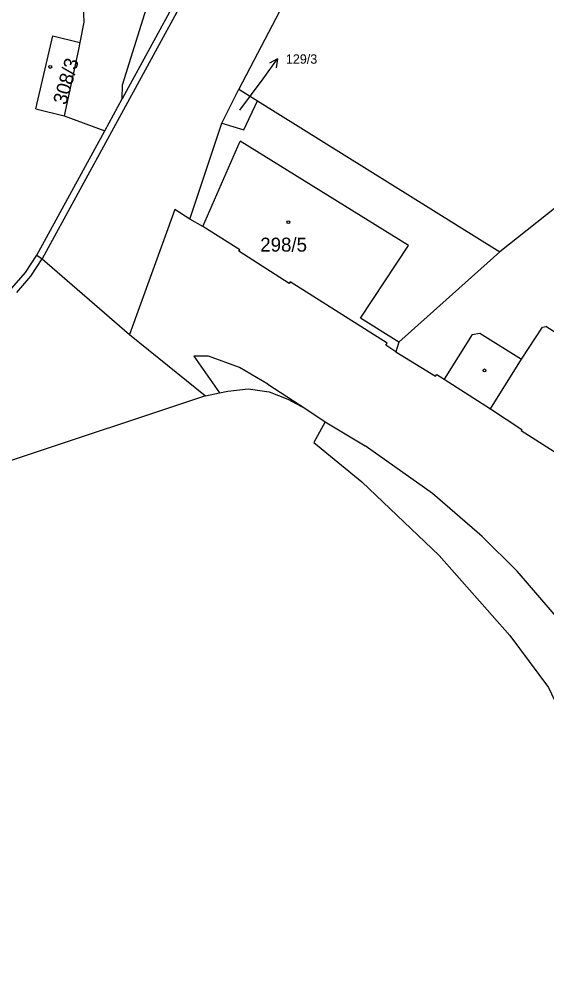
# Model space of a CAD drawing. Extents: x -679220 to -673243, y -1075091 to -1066557.
# Drawn here: x -676729.1 to -676665, y -1071520.5 to -1071402.6 of the extents above; entities that cross this region are included whole.
import ezdxf

# ---------------------------------------------------------------- set-up
doc = ezdxf.new("R2010")
doc.units = 0
for name, color, linetype in [('Hranice parcel', 7, 'Continuous'), ('Parcelní čísla', 7, 'Continuous'), ('Pop  PČ popisy', 7, 'Continuous'), ('Vnitřní kresba', 7, 'Continuous'), ('Značky budov', 7, 'Continuous')]:
    doc.layers.add(name, color=color, linetype=linetype)

msp = doc.modelspace()

# ---------------------------------------------------------------- linework, layer by layer
at = {"layer": 'Hranice parcel'}
for p, q in [((-676704.49, -1071415.22), (-676702.41, -1071411.05)), ((-676702.41, -1071411.05), (-676700.13, -1071412.47)), ((-676700.13, -1071412.47), (-676670.63, -1071430.85)), ((-676708.35, -1071426.89), (-676704.49, -1071415.22)), ((-676726.99, -1071431.27), (-676718.73, -1071416.13)), ((-676662.84, -1071424.65), (-676670.63, -1071430.85)), ((-676715.7, -1071440.94), (-676706.46, -1071448.39))]:
    msp.add_line(p, q, dxfattribs=at)
for points in [[(-676664.22, -1071348.86), (-676669.8, -1071355.84), (-676683.64, -1071376.26), (-676686.74, -1071381.26), (-676690.19, -1071387.69), (-676702.41, -1071411.05)], [(-676740.68, -1071376.97), (-676721.46, -1071393.56), (-676721.5, -1071397.04), (-676721.26, -1071402.92), (-676721.75, -1071405.37), (-676721.92, -1071406.25), (-676723.65, -1071414.33), (-676718.73, -1071416.13)], [(-676718.73, -1071416.13), (-676716.62, -1071412.26), (-676716.55, -1071410.54), (-676711.97, -1071395.85), (-676707.04, -1071389.88)], [(-676704.49, -1071415.22), (-676701.78, -1071416.03), (-676700.13, -1071412.47)], [(-676708.35, -1071426.89), (-676710.19, -1071425.7), (-676715.7, -1071440.94)], [(-676683.31, -1071443.03), (-676684.52, -1071442.21), (-676684.35, -1071441.96), (-676696.15, -1071434.53), (-676696.28, -1071434.73), (-676702.4, -1071430.77), (-676702.3, -1071430.63), (-676706.8, -1071427.78), (-676708.35, -1071426.89)], [(-676670.63, -1071430.85), (-676682.94, -1071441.86), (-676683.31, -1071443.03)], [(-676734.5, -1071439.01), (-676733.6, -1071438.44), (-676731.7, -1071436.98), (-676730.01, -1071435.3), (-676728.37, -1071433.36), (-676726.99, -1071431.27)], [(-676726.99, -1071431.27), (-676726.34, -1071431.73), (-676715.7, -1071440.94)], [(-676683.31, -1071443.03), (-676678.47, -1071446), (-676678.32, -1071445.78), (-676677.41, -1071446.35), (-676671.78, -1071449.97), (-676667.98, -1071452.47), (-676668.07, -1071452.62), (-676659.58, -1071457.99), (-676659.52, -1071457.9), (-676655.53, -1071460.4), (-676642.15, -1071468.89)], [(-676706.46, -1071448.39), (-676753.93, -1071464.16), (-676756.51, -1071465.26), (-676758.86, -1071466.72), (-676760.97, -1071468.64), (-676762.66, -1071470.73)], [(-676706.46, -1071448.39), (-676704.76, -1071448.03), (-676703.73, -1071447.81), (-676701.26, -1071447.54), (-676698.72, -1071447.92), (-676696.46, -1071448.78), (-676694.26, -1071449.98), (-676691.89, -1071451.57), (-676693.28, -1071454.07), (-676687.45, -1071458.85), (-676678.05, -1071467.82), (-676669.42, -1071477.57), (-676664.74, -1071483.89), (-676662.51, -1071488.58), (-676660.71, -1071493.4), (-676651.25, -1071520.53)]]:
    msp.add_lwpolyline(points, dxfattribs=at)
at = {"layer": 'Pop  PČ popisy'}
for p, q in [((-676699.46, -1071409.81), (-676697.7, -1071407.38)), ((-676697.7, -1071407.38), (-676698.69, -1071407.9)), ((-676697.7, -1071407.38), (-676697.88, -1071408.49)), ((-676702.29, -1071413.64), (-676699.46, -1071409.81))]:
    msp.add_line(p, q, dxfattribs=at)
at = {"layer": 'Vnitřní kresba'}
for p, q in [((-676709.38, -1071398.99), (-676716.62, -1071412.26)), ((-676708.68, -1071399.37), (-676726.34, -1071431.73)), ((-676727.12, -1071413.48), (-676725.02, -1071404.59)), ((-676725.02, -1071404.59), (-676721.75, -1071405.37)), ((-676727.12, -1071413.48), (-676723.65, -1071414.33)), ((-676706.8, -1071427.78), (-676702.24, -1071417.38)), ((-676681.76, -1071430.1), (-676702.24, -1071417.38)), ((-676687.6, -1071438.93), (-676681.76, -1071430.1)), ((-676727.73, -1071433.84), (-676726.34, -1071431.73)), ((-676729.4, -1071435.82), (-676727.73, -1071433.84)), ((-676682.94, -1071441.86), (-676687.6, -1071438.93)), ((-676668.01, -1071443.94), (-676665.47, -1071440.03)), ((-676665.47, -1071440.03), (-676665.07, -1071439.94)), ((-676661.44, -1071442.27), (-676665.07, -1071439.94)), ((-676674.02, -1071440.94), (-676677.41, -1071446.35)), ((-676674.02, -1071440.94), (-676673.09, -1071440.75)), ((-676673.09, -1071440.75), (-676668.01, -1071443.94)), ((-676706.09, -1071443.57), (-676707.9, -1071443.55)), ((-676707.9, -1071443.55), (-676704.76, -1071448.03)), ((-676702.33, -1071444.96), (-676706.09, -1071443.57)), ((-676698.88, -1071446.98), (-676702.33, -1071444.96)), ((-676671.78, -1071449.97), (-676668.01, -1071443.94)), ((-676698.88, -1071446.98), (-676694.26, -1071449.98)), ((-676691.89, -1071451.57), (-676687.02, -1071454.49)), ((-676678.86, -1071460.29), (-676687.02, -1071454.49)), ((-676672.81, -1071465.49), (-676678.86, -1071460.29)), ((-676668.56, -1071469.74), (-676672.81, -1071465.49)), ((-676663.26, -1071475.84), (-676668.56, -1071469.74))]:
    msp.add_line(p, q, dxfattribs=at)
at = {"layer": 'Značky budov'}
for centre in [(-676725.35, -1071408.36), (-676696.38, -1071427.26), (-676672.51, -1071445.29)]:
    msp.add_circle(centre, 0.175, dxfattribs=at)

# ---------------------------------------------------------------- texts
at = {"layer": 'Parcelní čísla'}
msp.add_text('308/3', height=1.7, rotation=74, dxfattribs=at).set_placement((-676723.42, -1071413.06))
for s, height, p in [('129/3', 1.14, (-676696.68, -1071407.97)), ('298/5', 1.7, (-676699.8, -1071430.84))]:
    msp.add_text(s, height=height, dxfattribs=at).set_placement(p)

doc.saveas('drawing.dxf')
